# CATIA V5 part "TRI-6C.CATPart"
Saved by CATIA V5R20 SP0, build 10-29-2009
Part number: _TRI-6C
Definition: NONE
Nomenclature: _TRI-6C
Source: Unknown
Description: PART-_TRI-6C-DESC
Bounding box of the stored display mesh (mm): x 0 to 11.4, y -3 to 3, z -3 to 3
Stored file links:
  C:\Users\Utente\Desktop\IO LAVORO\3D X SITO CF\X SITO\PLASTICA\TRI\TRI-6C.CATPart
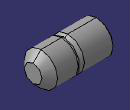
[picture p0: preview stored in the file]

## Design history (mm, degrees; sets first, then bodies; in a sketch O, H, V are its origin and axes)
Body1 "_TRI-6C" (main body)
  Solid1: solid without history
